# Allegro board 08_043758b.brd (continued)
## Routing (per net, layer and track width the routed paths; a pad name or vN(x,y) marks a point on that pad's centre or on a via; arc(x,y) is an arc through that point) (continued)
1P3_SUPPLY_B: length 107.7
  TOP w0.203: U1.9 20.63,14.51 20.47,14.68 20.1,14.68
  TOP w0.305: C5.1 19.1,16.14 ; C5.1 18.64,15.73 ; C5.1 18.18,16.14 ; U5.A7 v2(34.74,31.28) ; U5.E3 v2(31.54,35.28) ; 16.98,12.21 U1.14 U1.13 ; U5.A8 v2(33.94,31.28) ; U5.K4 v2(26.74,34.48) ; U1.11 U1.12 ; U1.11 19.33,14.56 ; U1.11 U1.10 19.98,14.56 ; U1.12 18.68,14.56 ; U1.12 18.25,13.78 ; U5.A9 v2(34.74,30.48) ; 16.98,12.86 U1.13 ; U1.13 17.76,13.29 ; U5.A10 v2(34.74,29.68) ; 19.91,15.73 C6.1 ; C6.1 20.37,16.14 ; C6.1 19.45,16.14 ; U5.D2 v2(32.34,36.08) ; U5.F12 v2(30.74,27.28) ; 20.93,16.08 UNK1P3V_B.1 21.69,15.31 ; U5.M10 v2(25.14,28.88) ; U5.M9 v2(25.14,29.68) ; U5.B8 v2(33.94,30.48) ; U5.D3 v2(32.34,35.28)
  TOP w0.635: L8.1 22.17,27.63 v1(21.14,27.63) ; C3.1 16.93,14.3 ; C3.1 16.29,15 ; C3.1 16.29,13.6 ; L9.1 v1(21.14,33.09) ; 16.42,16.01 C4.1 ; C4.1 17.12,15.38 ; C4.1 17.82,16.01
  BOTTOM w0.305: C30.1 30.73,25.95 C26.1 30.73,27.26 v2(30.74,27.28) ; v2(26.74,34.48) 26.45,34.18 26.01,34.18 C41.1 25.68,33.84 C36.1 ; v2(33.94,30.48) 33.86,30.56 C27.1 33.86,31.2 v2(33.94,31.28) ; v1(21.14,27.63) 21.18,27.59 C129.2 20.74,27.06 19.98,26.3 C130.1
  BOTTOM w0.406: v2(34.74,30.48) 34.74,30.48 v2(33.94,30.48) ; v2(34.74,30.48) 34.74,31.28 v2(34.74,31.28) ; v2(34.74,30.48) 35.15,30.48 35.41,30.74 35.41,31.2 35.49,31.28 ; v2(34.74,30.48) 34.74,29.68 v2(34.74,29.68) ; C31.1 35.49,31.28 ; 35.49,31.28 34.75,31.28 v2(34.74,31.28) ; v2(34.74,31.28) v2(33.94,31.28) ; v2(31.54,35.28) v2(32.34,35.28) 32.34,35.37 ; 32.34,35.37 v2(32.34,36.08) ; 32.34,35.37 32.47,35.49 C42.1 33.83,35.49 C37.1
  BOTTOM w0.508: C36.1 23.96,34.36 16.73,34.36 v1(14.91,36.18) v1(14.09,36.18) ; v1(21.14,33.09) v1(21.14,27.63) 23.9,27.63 v2(25.14,28.88) 25.14,29.68 v2(25.14,29.68) ; v1(33.24,43.19) v1(33.24,42.39) 33.24,39.38 35.5,37.13 35.5,35.73 35.14,35.37 C37.1 ; C31.1 36.3,31.33 36.75,31.78 36.75,37.68 34.55,39.88 v1(34.55,42.39) v1(34.55,43.19)
  BOTTOM w0.635: C130.1 15.11,26.3 v1(14.91,26.5) v1(14.09,26.5) ; E3.2 v1(33.63,56.97) ; C30.1 30.9,23.63 29.94,22.68 23.85,22.68 v1(21.82,20.65) v1(21.05,20.65)
  vias: v1(16.23,16.08) v1(16.23,15.19) v1(17.12,15.19) v1(17.24,14.3) v1(18.01,16.08) v1(18.01,15.19) v1(19.28,16.08) v1(20.55,16.08)
1P8V_CLK: length 11.9
  TOP w0.305: Y3.4 25.06,17.67 C122.1 25.06,14.58 C121.1 25.37,14.21 v1(25.37,13.28) ; 47.61,15.71 U12.1 48.29,16.12 ; 45.82,16.33 UNK1P8V_CLK.1 45.06,15.57
  TOP w0.508: 46,15.55 C170.1 ; C170.1 46.58,16.1 ; C170.1 47.17,15.55
  L6_SIG w0.305: UNK1P8V_CLK.1 45.82,16.33 ; UNK1P8V_CLK.1 45.06,15.57 ; UNK1P8V_CLK.1 45.06,17.09 ; UNK1P8V_CLK.1 44.3,16.33
  vias: v1(46.2,16.33) v1(46.96,16.33)
AD9363_AUXADC: length 49.2
  TOP w0.127: U5.L5 v2(25.95,32.88)
  L6_SIG w0.127: ADC.1 42.64,67 36.04,67 35.53,66.49 35.53,63.32 29.85,57.63 29.85,50.29 30.55,49.59 30.55,39.78 27.95,37.18 27.95,34.28 27.77,34.1 27.27,34.1 27.14,33.98 27.14,33.48 26.94,33.28 U5.L5 v2(25.95,32.88)
AD9363_AUXDAC1: length 39.8
  TOP w0.127: U5.B3 33.95,35.08 34.15,35.28 35.25,35.28 35.55,35.58 35.55,38.79 36.62,39.86 v1(36.62,41.16)
  L6_SIG w0.127: DAC1.1 37.92,64.11 37.92,61.77 37.31,61.16 34.39,61.16 30.91,57.68 30.91,50.86 33.91,47.86 33.91,45.96 36.62,43.26 v1(36.62,41.16)
AD9363_AUXDAC2: length 35.1
  TOP w0.127: v1(35.92,42.16) 35.92,39.66 35.25,38.99 35.25,38.18 33.95,36.88 33.95,35.48 33.74,35.28 33.15,35.28 U5.C3
  L6_SIG w0.127: v1(35.92,42.16) 35.92,43.46 33.51,45.86 33.51,47.66 30.51,50.66 30.51,57.79 35.41,62.68 DAC2.1
AD9363_GPO_0: length 45.7
  TOP w0.127: U5.B7 33.94,32.08 35.65,32.08 36.75,33.18 36.75,37.88 39.02,40.16 v1(39.02,41.16)
  L6_SIG w0.127: v1(39.02,41.16) 39.02,42.86 35.52,46.36 35.52,48.66 32.51,51.66 32.51,57.25 34.87,59.61 41.35,59.61 GPO0.1
AD9363_GPO_1: length 43
  TOP w0.127: U5.B6 33.94,32.88 35.45,32.88 36.45,33.88 36.45,38.18 38.42,40.16 v1(38.42,42.16)
  L6_SIG w0.127: GPO1.1 41.88,61.54 40.35,60.01 34.76,60.01 32.11,57.36 32.11,51.46 35.12,48.46 35.12,46.26 38.42,42.96 v1(38.42,42.16)
AD9363_GPO_2: length 39.8
  TOP w0.127: U5.B5 33.94,33.68 35.35,33.68 36.15,34.48 36.15,38.38 37.82,40.06 v1(37.82,41.16)
  L6_SIG w0.127: v1(37.82,41.16) 37.82,43.06 34.72,46.16 34.72,48.26 31.71,51.26 31.71,57.47 34.66,60.41 38.21,60.41 39.34,61.54 GPO2.1
AD9363_GPO_3: length 40.9
  TOP w0.127: U5.B4 33.94,34.48 35.15,34.48 35.85,35.18 35.85,38.59 37.22,39.96 v1(37.22,42.16)
  L6_SIG w0.127: v1(37.22,42.16) 37.22,43.16 34.31,46.06 34.31,48.06 31.31,51.06 31.31,57.58 34.55,60.81 37.47,60.81 38.22,61.56 38.22,64.1 GPO3.1
ADM1177_SCL: length 61
  TOP w0.127: v1(73.89,15.06) 73.04,14.21 66.79,14.21 66.69,14.11 65.26,14.11 R81.2 64.18,15.19 U11.7
  L5_SIG w0.127: v1(86.36,56.63) 85.71,56.63 84.78,55.7 84.78,38.93 78.11,32.26 78.11,27.65 78.62,27.14 78.62,21.47 76.95,19.8 76.95,18.78 73.89,15.72 v1(73.89,15.06)
  BOTTOM w0.127: v1(86.36,56.63) 86.36,57.32 86.13,57.55 U10.6
ADM1177_SDA: length 64.7
  TOP w0.127: v1(74.78,15.69) 74.78,15.06 73.54,13.83 65.24,13.83 R80.2 63.98,13.87 63.98,14.3 63.74,14.54 U11.6
  L5_SIG w0.127: v1(87.6,56.63) 86.97,55.99 85.58,55.99 85.14,55.55 85.14,38.78 78.47,32.12 78.47,27.8 78.98,27.29 78.98,21.32 77.33,19.67 77.33,18.53 75.55,16.75 75.55,16.47 v1(74.78,15.69)
  BOTTOM w0.127: U10.7 87.03,58.05 87.6,57.48 v1(87.6,56.63)
ADP2114_VIN: length 20
  TOP w0.203: 93.57,40.97 93.3,41.24 U6.31
  TOP w0.305: C141.1 95.24,47.57 93.6,47.57 93.3,47.27 U6.10 ; C141.1 96.18,46.99 R56.2 96.18,48.27 v1(95.98,48.46) ; C141.1 95.21,46.02 U6.8 ; 93.57,40.97 93.95,40.59 v1(94.71,40.59) ; v1(95.35,44.14) 95.23,44.02 U6.4
  L5_SIG w0.305: v1(94.71,40.59) 95.22,40.59 96.1,41.46 96.1,43.02 95.35,43.76 v1(95.35,44.14) 95.68,44.14 95.98,44.45 v1(95.98,48.46)
COMP_1P8V: length 2.8
  TOP w0.305: U6.2 95.2,43.02 v1(95.35,42.87)
  BOTTOM w0.508: v1(95.35,42.87) 95.48,42.75 R60.1 C142.2
COMP_1P35V: length 3.1
  TOP w0.305: C144.1 C143.2 96.1,45.52 U6.7
CTRL_IN0: length 52
  TOP w0.102: U4.F13 v2(56.33,28.95) ; U5.C5 v2(33.14,33.68)
  L6_SIG w0.114: v2(33.14,33.68) 33.15,33.68 33.55,34.08 33.55,34.68 33.35,34.88 31.35,34.88 30.34,33.88 30.34,32.68 30.15,32.48 28.65,32.48 27.95,31.78 27.95,24.43 30.2,22.17 53.36,22.17 56.72,25.53 56.72,26.91 56.33,27.31 v2(56.33,28.95)
CTRL_IN1: length 47.2
  TOP w0.102: U5.C6 v2(33.14,32.88) ; U4.F14 55.93,28.54 56.33,28.14 v2(56.33,26.55)
  L6_SIG w0.114: v2(56.33,26.55) 56.33,25.74 53.27,22.68 30.33,22.68 28.35,24.66 28.35,30.68 28.74,31.07 28.74,31.58 28.84,31.68 29.35,31.68 29.71,32.05 30.11,32.05 30.82,32.75 30.82,33.15 31.75,34.08 32.55,34.08 32.75,33.88 32.75,33.28 33.14,32.89 v2(33.14,32.88)
CTRL_IN2: length 37.7
  TOP w0.102: U5.D6 v2(32.34,32.88) ; v2(55.53,27.35) U4.G15
  L6_SIG w0.114: v2(55.53,27.35) 54.96,26.78 54.96,26.37 54.66,26.07 54.06,26.07 52.19,24.2 31.82,24.2 31.25,24.77 31.25,25.57 30.05,26.77 30.05,28.07 29.55,28.57 29.55,30.68 29.75,30.88 30.15,30.88 30.35,31.08 30.35,31.48 31.22,32.35 31.61,32.35 32.14,32.88 v2(32.34,32.88)
CTRL_IN3: length 41.3
  TOP w0.102: v2(55.53,26.55) 55.93,26.95 U4.F15 ; U5.D5 v2(32.34,33.68)
  L6_SIG w0.114: v2(32.34,33.68) U5.D5 31.34,33.28 31.12,33.05 31.12,32.65 30.17,31.7 29.76,31.7 29.55,31.48 29.55,31.08 29.35,30.88 28.95,30.88 28.75,30.68 28.75,28.17 29.25,27.67 29.25,25.28 30.71,23.82 52.61,23.82 53.98,25.18 54.97,25.18 55.53,25.75 v2(55.53,26.55)
DDR3_A0: length 30.1
  TOP w0.165: U2.N3 51.22,54.27 v2(51.22,54.27) ; v2(43.92,40.85) 47.03,40.85 48.43,39.45 49.03,39.45 U4.P1
  L6_SIG w0.165: v2(43.92,40.85) 43.32,41.45 43.32,42.04 43.52,42.23 43.91,42.23 44.11,42.43 44.11,42.71 43.91,42.91 43.52,42.91 43.32,43.1 43.32,43.38 43.52,43.58 43.91,43.58 44.11,43.78 44.11,44.06 43.91,44.25 43.52,44.25 43.32,44.45 43.32,47.48 46.51,50.67 49.02,50.67 49.41,51.07 49.41,51.87 51.22,53.68 v2(51.22,54.27)
  BOTTOM w0.165: R16.1 51.62,56.16 51.62,54.67 v2(51.22,54.27)
DDR3_A1: length 33.2
  TOP w0.165: v2(43.92,41.65) 46.93,41.65 48.63,39.95 49.33,39.95 U4.N1 ; v2(48.03,51.66) 49.83,51.66 U2.P7
  L6_SIG w0.165: v2(43.92,41.65) 44.41,41.16 44.41,39.66 44.21,39.46 43.61,39.46 42.51,40.56 42.51,48.17 42.72,48.38 42.72,48.78 43.07,49.13 43.47,49.13 43.67,49.33 43.67,49.61 43.4,49.88 43.4,50.16 43.6,50.35 43.88,50.35 44.15,50.08 44.43,50.08 44.62,50.28 44.62,50.56 44.35,50.83 44.35,51.11 44.55,51.31 44.83,51.31 45.1,51.03 45.38,51.03 46,51.66 v2(48.03,51.66)
  BOTTOM w0.165: R22.1 47.45,51.66 v2(48.03,51.66)
DDR3_A2: length 35.7
  TOP w0.165: U2.P3 v2(50.42,54.27) ; U4.M1 51.13,39.75 v2(49.93,40.95)
  L5_SIG w0.165: v2(49.93,40.95) 49.53,40.95 49.23,40.65 49.23,40.35 49.93,39.65 49.93,39.35 49.53,38.95 49.53,37.95 49.13,37.55 48.93,37.55 48.73,37.75 48.73,38.75 48.53,38.95 48.23,38.95 48.03,38.75 48.03,37.65 47.87,37.49 47.59,37.49 45.83,39.25 45.83,51.2 48.5,53.87 50.02,53.87 v2(50.42,54.27)
  BOTTOM w0.165: v2(50.42,54.27) 50.02,53.87 49.3,53.87 48.61,54.56 47.45,54.56 R17.1
DDR3_A3: length 31.5
  TOP w0.165: U4.M4 v2(50.73,36.95) ; U2.N2 v2(51.22,55.07)
  L5_SIG w0.165: v2(50.73,36.95) 51.02,36.95 51.13,37.06 51.13,37.97 51.48,38.33 51.48,38.63 51.28,38.83 50.9,38.83 50.73,39 50.73,42.75 50.53,42.95 49.93,42.95 49.53,43.35 49.53,44.55 49.71,44.73 50.13,44.73 50.33,44.93 50.33,45.21 50.13,45.4 49.73,45.4 49.53,45.6 49.53,45.88 49.73,46.08 50.13,46.08 50.33,46.27 50.33,46.55 50.13,46.75 49.73,46.75 49.53,46.95 49.53,47.23 49.73,47.42 50.13,47.42 50.33,47.62 50.33,48.06 50.12,48.27 49.92,48.27 49.73,48.46 49.73,49.56 50.04,49.87 50.64,49.87 50.82,50.04 50.82,51.73 51,51.92 51.51,51.92 51.69,52.09 51.69,52.58 51.85,52.74 52.59,52.74 52.75,52.9 52.75,53.12 52.59,53.28 51.85,53.28 51.69,53.44 51.69,53.74 51.85,53.9 52.6,53.9 52.76,54.06 52.76,54.28 52.6,54.44 51.65,54.44 51.46,54.63 51.46,54.83 v2(51.22,55.07)
  BOTTOM w0.165: v2(51.22,55.07) 50.94,55.07 50.82,55.2 50.82,56.16 R23.1
DDR3_A4: length 26.7
  TOP w0.165: v2(47.33,38.65) 48.23,37.75 49.13,37.75 U4.P3 ; v2(50.42,50.27) U2.P8
  L6_SIG w0.165: v2(50.42,50.27) 50.83,49.86 50.83,48.28 50.62,48.07 49.82,48.07 46.41,44.66 46.41,41.76 46.71,41.46 48.91,41.46 49.13,41.25 49.13,40.75 48.84,40.46 48.04,40.46 47.81,40.23 47.81,39.66 47.61,39.46 46.71,39.46 46.51,39.26 46.51,38.46 46.72,38.25 46.93,38.25 v2(47.33,38.65)
  BOTTOM w0.165: R18.1 47.64,50.67 50.02,50.67 v2(50.42,50.27)
DDR3_A5: length 24
  TOP w0.165: U2.P2 v2(50.42,55.07) ; v2(49.11,36.96) U4.P4
  L5_SIG w0.165: v2(49.11,36.96) 49.5,37.35 50.13,37.35 50.33,37.55 50.33,38.05 50.33,38.05 50.45,38.17 50.45,38.73 50.33,38.85 50.33,42.35 50.13,42.55 49.73,42.55 49.13,43.15 49.13,48.16 49.33,48.36 49.33,49.78 50.43,50.88 50.43,51.98 51.23,52.78 51.23,53.56 50.82,53.97 50.82,54.67 v2(50.42,55.07)
  BOTTOM w0.165: v2(50.42,55.07) 50.14,55.07 50.02,55.2 50.02,56.16 R24.1
DDR3_A6: length 26.8
  TOP w0.165: U2.R8 49.62,49.47 48.81,49.47 v2(48.01,48.67) ; v2(46.72,36.55) 47.13,36.15 49.13,36.15 U4.P5
  L6_SIG w0.165: v2(46.72,36.55) 44.91,38.36 44.91,38.86 45.21,39.16 45.21,44.26 44.21,45.26 44.21,47.07 44.82,47.67 45.1,47.67 45.37,47.4 45.65,47.4 45.84,47.6 45.84,47.88 45.61,48.11 45.61,48.47 46.01,48.87 46.29,48.87 46.42,48.74 46.42,47.96 46.63,47.76 47.13,47.76 47.33,47.96 47.33,48.26 47.09,48.49 47.09,48.87 47.29,49.07 47.62,49.07 v2(48.01,48.67)
  BOTTOM w0.165: v2(48.01,48.67) 48.52,48.17 48.63,48.17 R19.1
DDR3_A7: length 30.3
  TOP w0.165: U4.M5 v2(50.73,36.15) ; U2.R2 v2(49.62,55.07)
  L5_SIG w0.165: v2(50.73,36.15) 50.33,35.75 49.03,35.75 48.63,36.15 47.73,36.15 46.57,37.3 45.67,37.3 45.02,37.95 45.02,51.58 48.82,55.37 49.31,55.37 v2(49.62,55.07)
  BOTTOM w0.165: v2(49.62,55.07) 49.33,55.36 48.63,55.36 48.12,55.87 R25.1
DDR3_A8: length 24.1
  TOP w0.165: U4.P6 49.13,35.35 47.12,35.35 v2(46.72,35.75) ; v2(48.01,49.47) 48.41,49.87 U2.T8
  L6_SIG w0.165: v2(46.72,35.75) 46.42,36.16 44.51,38.06 44.51,39.16 44.81,39.46 44.81,44.06 43.81,45.06 43.81,47.27 46.01,49.47 v2(48.01,49.47)
  BOTTOM w0.165: v2(48.01,49.47) 47.52,48.97 47.52,48.55 R20.1
DDR3_A9: length 27.7
  TOP w0.165: U4.N4 v2(49.93,36.95) ; v2(49.61,54.27) U2.R3
  L5_SIG w0.165: v2(49.61,54.27) 48.34,54.27 45.43,51.36 45.43,39.05 47.43,37.05 48.33,37.05 48.93,36.45 49.43,36.45 v2(49.93,36.95)
  BOTTOM w0.165: R26.1 47.87,54.94 48.95,54.94 v2(49.61,54.27)
DDR3_A10: length 39.2
  TOP w0.165: U4.J1 53.13,39.35 v2(53.13,40.35) ; v2(52.81,51.07) 53.21,50.67 U2.L7
  L5_SIG w0.165: v2(52.81,51.07) 53.23,50.66 53.48,50.66 53.63,50.51 53.63,50.1 53.13,49.6 53.13,48.8 52.93,48.6 52.63,48.6 52.43,48.41 52.43,48.13 52.63,47.93 53.43,47.93 53.63,47.73 53.63,47.35 53.43,47.15 52.43,47.15 52.43,47.16 52.13,47.46 51.83,47.46 51.63,47.26 51.63,46.62 51.83,46.41 52.23,46.41 52.43,46.22 52.43,45.94 52.23,45.74 51.83,45.74 51.63,45.54 51.63,45.15 51.92,44.87 52.24,44.87 52.73,45.36 53.03,45.36 53.23,45.16 53.23,44.41 53.1,44.28 52.35,44.28 52.13,44.06 52.13,43.86 52.32,43.67 53.1,43.67 53.32,43.45 53.32,43.22 53.03,42.93 52.73,42.93 52.53,42.74 52.53,42.46 52.73,42.26 52.93,42.26 53.13,42.06 53.13,41.79 52.93,41.59 52.73,41.59 52.32,41.18 52.32,40.36 52.73,39.95 52.73,35.95 52.93,35.75 54.13,35.75 54.33,35.95 54.33,36.25 54.13,36.45 53.68,36.45 53.53,36.6 53.53,39.95 v2(53.13,40.35)
  BOTTOM w0.165: v2(52.81,51.07) 52.22,51.07 51.62,50.47 51.62,48.28 R21.1
DDR3_A11: length 32.7
  TOP w0.165: v2(47.43,42.05) 48,41.48 50,41.48 51.53,39.95 51.53,38.55 U4.L2 ; U2.R7 49.62,50.27 v2(48.02,50.27)
  L5_SIG w0.165: v2(47.43,42.05) 47.43,41.34 46.81,40.72 46.81,39.87 47.13,39.55 47.63,39.55 47.98,39.9 47.98,41.1 48.33,41.45 48.73,41.45 48.93,41.65 48.93,42.75 48.43,43.25 47.73,43.25 47.53,43.45 47.53,43.76 47.72,43.95 48.53,43.95 48.73,44.15 48.73,44.43 48.53,44.63 47.82,44.63 47.63,44.82 47.63,45.1 47.82,45.3 48.53,45.3 48.73,45.5 48.73,45.77 48.53,45.97 47.82,45.97 47.63,46.17 47.63,46.45 47.82,46.65 48.53,46.65 48.73,46.84 48.73,47.12 48.53,47.32 47.82,47.32 47.63,47.52 47.63,47.96 47.83,48.16 48.23,48.16 48.42,48.35 48.42,48.87 48.22,49.07 47.81,49.07 47.62,49.27 47.62,49.87 v2(48.02,50.27)
  BOTTOM w0.165: R27.1 47.23,49.49 v2(48.02,50.27)
DDR3_A12: length 30.5
  TOP w0.165: U4.M2 50.75,38.52 50.75,39.34 49.14,40.95 v2(48.43,40.95) ; U2.N7 51.22,51.07 v2(51.22,51.07)
  L6_SIG w0.165: v2(48.43,40.95) 46.32,40.95 46.01,41.26 46.01,45.46 45.81,45.66 45.31,45.66 45.09,45.88 45.09,46.35 45.31,46.57 47.71,46.57 50.03,48.88 50.03,49.19 49.83,49.38 49.51,49.38 49.31,49.58 49.31,49.86 49.51,50.06 49.83,50.06 50.01,50.24 50.01,50.54 50.53,51.06 50.53,51.79 51.5,52.76 51.73,52.76 51.98,52.51 51.98,52.21 51.22,51.44 v2(51.22,51.07)
  BOTTOM w0.165: v2(51.22,51.07) 50.82,50.67 50.82,48.28 R28.1
DDR3_A13: length 30.8
  TOP w0.165: v2(49.93,41.98) 50.23,41.98 52.33,39.89 52.33,38.55 U4.K2 ; v2(48.82,53.47) 48.82,53.47 U2.T3
  L5_SIG w0.165: v2(48.82,53.47) 48.2,52.86 48.03,52.86 46.23,51.06 46.23,50.52 46.35,50.39 46.63,50.39 46.83,50.2 46.83,49.92 46.63,49.72 46.42,49.72 46.23,49.52 46.23,49.24 46.42,49.05 46.63,49.05 46.83,48.85 46.83,48.57 46.63,48.37 46.42,48.37 46.23,48.18 46.23,47.9 46.42,47.7 46.63,47.7 46.83,47.5 46.83,47.23 46.63,47.03 46.42,47.03 46.23,46.83 46.23,46.55 46.63,46.15 46.63,45.75 46.23,45.35 46.23,39.65 46.72,39.15 47.83,39.15 48.83,40.15 48.83,40.88 v2(49.93,41.98)
  BOTTOM w0.165: v2(48.82,53.47) 48.22,54.07 R34.1
DDR3_A14: length 35.5
  TOP w0.165: U4.K1 52.73,40.09 50.32,42.49 48.87,42.49 v2(48.43,42.05) ; v2(48.82,51.07) U2.T7
  L5_SIG w0.165: v2(48.82,51.07) 49.23,50.66 49.23,50.26 48.92,49.95 48.74,49.95 48.53,50.16 48.53,50.46 48.13,50.86 48.13,51.16 48.83,51.86 49.08,51.86 49.59,51.36 49.83,51.36 50.03,51.56 50.03,51.87 49.57,52.32 49.57,52.6 49.73,52.76 50.03,52.76 50.23,52.56 50.5,52.56 50.71,52.78 50.71,53.24 50.5,53.45 49.62,53.45 48.24,52.07 47.84,52.07 47.61,51.84 47.61,51.5 47.38,51.27 47.04,51.27 46.83,51.06 46.83,50.86 47.22,50.47 47.22,45.38 47.03,45.19 46.82,45.19 46.63,45 46.63,44.72 46.82,44.52 47.03,44.52 47.23,44.32 47.23,44.04 47.03,43.85 46.82,43.85 46.63,43.65 46.63,42.55 46.79,42.39 47.07,42.39 47.43,42.75 48.3,42.75 48.43,42.63 v2(48.43,42.05)
  BOTTOM w0.165: R29.1 48.02,51.07 48.46,51.51 48.69,51.51 48.82,51.39 v2(48.82,51.07)
DDR3_BA0: length 34
  TOP w0.165: U2.M2 v2(52.02,55.07) ; U4.M6 v2(50.73,35.35)
  L5_SIG w0.165: v2(50.73,35.35) 51.13,35.75 51.73,35.75 51.93,35.94 51.93,38.75 51.13,39.55 51.13,43.24 50.93,43.44 50.13,43.44 49.93,43.64 49.93,43.92 50.13,44.11 50.6,44.11 50.82,44.33 50.82,48.17 50.93,48.28 50.93,49.36 51.62,50.04 51.62,50.52 51.84,50.74 51.84,51.69 52.14,51.99 53.57,51.99 53.87,52.3 53.87,52.75 53.64,52.98 53.39,52.98 53.22,53.15 53.22,57.57 53.02,57.78 52.77,57.78 52.58,57.58 52.58,55.63 v2(52.02,55.07)
  BOTTOM w0.165: R35.1 52.72,55.57 52.52,55.37 52.32,55.37 v2(52.02,55.07)
DDR3_BA1: length 30.4
  TOP w0.165: v2(51.22,50.27) U2.N8 ; U4.R1 48.35,38.95 v2(47.34,39.96)
  L6_SIG w0.165: v2(51.22,50.27) 51.22,48.07 50.8,47.65 50,47.65 48.13,45.78 48.13,44.95 47.76,44.59 47.34,44.59 47.11,44.36 47.11,44.14 47.34,43.91 47.76,43.91 48,43.68 48,43.36 47.83,43.2 47.44,43.2 47.21,42.97 47.21,42.75 47.44,42.52 49.33,42.52 49.53,42.33 49.53,40.27 49.11,39.86 48.51,39.86 48.23,39.57 48.23,38.85 47.33,37.95 47.33,37.47 47.05,37.2 46.67,37.2 46.11,37.76 46.11,40.36 46.28,40.53 47.14,40.53 47.34,40.34 v2(47.34,39.96)
  BOTTOM w0.165: R30.1 51.22,47.89 v2(51.22,50.27)
DDR3_BA2: length 28.7
  TOP w0.165: U2.M3 52.42,53.37 v2(53.32,52.47) ; U4.N6 v2(49.93,35.35)
  L6_SIG w0.165: v2(49.93,35.35) 50.33,35.75 50.98,35.75 51.13,35.9 51.13,36.38 50.97,36.55 50.57,36.55 50.33,36.78 50.33,38.97 51.02,39.66 51.41,39.66 51.72,39.96 51.72,40.86 51.32,41.26 51.32,43.66 50.63,44.35 50.33,44.35 49.93,43.95 49.63,43.95 49.43,44.15 49.43,45.18 50.7,46.45 52.13,46.45 52.33,46.65 52.33,47.15 53.21,48.04 53.21,51.36 54.02,52.17 54.02,52.57 53.82,52.76 53.61,52.76 v2(53.32,52.47)
  BOTTOM w0.165: R36.1 52.54,51.69 v2(53.32,52.47)
DDR3_CAS#: length 28.5
  TOP w0.165: v2(53.62,53.46) 54.02,53.86 U2.K3 ; v2(48.21,35.75) U4.R5
  L6_SIG w0.165: v2(48.21,35.75) 48.78,35.18 49.16,35.18 49.43,35.45 49.43,36.02 49.3,36.15 48.93,36.15 48.65,36.43 48.65,37.47 48.81,37.64 49.36,37.64 49.53,37.8 49.53,38.87 50.83,40.17 50.83,43.15 50.52,43.46 49.22,43.46 49.01,43.67 49.01,45.36 50.52,46.87 51.32,46.87 52.73,48.28 52.73,50.36 52.22,50.87 52.22,51.14 52.82,51.74 52.82,52.66 v2(53.62,53.46)
  BOTTOM w0.165: v2(53.62,53.46) 53.63,53.45 53.63,53.01 53.49,52.87 52.94,52.87 R32.1
DDR3_CK_N: length 32.4
  TOP w0.127: v2(53.61,51.07) 54.02,50.67 U2.K7 ; U4.N2 v2(49.93,38.55)
  BOTTOM w0.127: R142.2 53.61,51.66 v2(53.61,51.07) 53.22,50.68 53.22,50.44 53.43,50.23 53.61,50.23 53.94,50.56 54.12,50.56 54.42,50.26 54.42,47.57 55.09,46.9 58.79,46.9 59.14,46.55 59.14,46.06 58.82,45.74 54.85,45.74 54.32,45.21 54.32,44.15 54.06,43.89 51.99,43.89 50.81,45.06 49.92,45.06 49.12,44.26 49.12,43.5 50.95,41.66 50.95,38.95 50.3,38.3 50.18,38.3 v2(49.93,38.55)
DDR3_CK_P: length 31.5
  TOP w0.127: U4.N3 v2(49.93,37.75) ; U2.J7 v2(54.42,51.07)
  BOTTOM w0.127: v2(49.93,37.75) 50.2,38.02 50.41,38.02 51.23,38.84 51.23,41.78 49.4,43.62 49.4,44.15 50.03,44.78 50.7,44.78 51.87,43.61 54.18,43.61 54.6,44.03 54.6,45.09 54.97,45.46 58.94,45.46 59.42,45.94 59.42,46.66 58.91,47.18 55.21,47.18 54.7,47.69 54.7,50.38 54.42,50.66 v2(54.42,51.07) 54.42,51.47 R142.1
DDR3_CKE: length 34.9
  TOP w0.165: U4.L3 v2(51.53,37.75) ; v2(53.62,48.67) U2.K9
  L6_SIG w0.165: v2(51.53,37.75) U4.L3 53.4,37.35 53.63,37.58 53.63,37.93 53.41,38.15 52.83,38.15 52.64,38.35 51.03,38.35 50.86,38.52 50.86,38.79 51.02,38.96 53.4,38.96 53.64,39.2 53.64,39.58 53.38,39.85 52.33,39.85 52.13,40.04 52.13,40.32 52.33,40.52 52.53,40.52 52.73,40.72 52.73,41.01 52.53,41.21 52.13,41.21 51.93,41.4 51.93,41.68 52.13,41.88 53,41.88 53.13,42.01 53.13,42.42 53,42.55 52.33,42.55 52.13,42.75 52.13,43.05 52.3,43.22 53.28,43.22 53.43,43.38 53.43,43.75 53.28,43.9 51.73,43.9 51.53,44.09 51.53,44.37 51.73,44.57 52.93,44.57 53.13,44.77 53.13,45.05 52.93,45.24 51.32,45.24 51.03,44.95 50.73,44.95 50.53,45.15 50.53,45.45 50.99,45.92 53.29,45.92 53.62,46.24 v2(53.62,48.67)
  BOTTOM w0.165: R38.1 53.63,47.88 53.82,48.07 53.82,48.47 v2(53.62,48.67)
DDR3_CS#: length 29.4
  TOP w0.165: U4.R2 48.47,38.15 47.37,39.25 46.32,39.25 45.63,39.95 v2(43.92,39.95) ; U2.L2 v2(52.82,55.07)
  L6_SIG w0.165: v2(43.92,39.95) 42.92,40.95 42.92,47.68 46.31,51.07 48.11,51.07 50.82,53.78 50.82,54.48 51.01,54.67 52.23,54.67 v2(52.82,55.07)
  BOTTOM w0.165: v2(52.82,55.07) 53.09,55.07 53.22,55.2 53.22,56.15 R39.1
DDR3_DM0: length 26.5
  TOP w0.165: U4.B1 60.01,39.82 62.25,39.82 v2(63.13,38.95) ; U2.E7 59.22,51.87 v2(59.22,52.67)
  L6_SIG w0.165: v2(59.22,52.67) 59.62,52.27 62.63,52.27 63.52,51.37 63.52,50.49 63.2,50.16 63.2,49.89 63.4,49.69 63.68,49.69 63.9,49.91 64.18,49.91 64.53,49.56 64.53,40.35 v2(63.13,38.95)
DDR3_DM1: length 23.1
  TOP w0.165: v2(59.22,53.47) U2.D3 ; U4.D3 v2(57.93,37.75)
  L5_SIG w0.165: v2(59.22,53.47) 58.52,52.78 58.52,51.05 58.02,50.54 58.02,48.16 55.63,45.78 55.63,42.35 54.23,40.95 54.23,37.55 54.42,37.35 57.53,37.35 v2(57.93,37.75)
DDR3_DQ0: length 28.4
  TOP w0.165: U2.E3 58.42,54.27 v2(58.42,54.27) ; U4.D4 v2(57.93,36.95)
  L6_SIG w0.165: v2(58.42,54.27) 58.81,54.27 58.99,54.09 58.99,53.88 58.77,53.67 58.77,52.42 59.72,51.47 61.92,51.47 62.63,50.76 62.63,49.26 63.03,48.85 63.31,48.85 63.48,49.02 63.76,49.02 63.96,48.83 63.96,48.55 63.79,48.38 63.79,48.1 64.13,47.76 64.13,40.65 62.63,39.15 62.63,37.95 61.23,36.55 58.33,36.55 v2(57.93,36.95)
DDR3_DQ1: length 24.7
  TOP w0.165: v2(58.02,52.27) 57.22,51.47 U2.F7 ; U4.A2 61.73,38.15 v2(62.13,38.55)
  L6_SIG w0.165: v2(58.02,52.27) 59.62,50.67 61.92,50.67 62.12,50.47 62.12,48.6 62.29,48.43 62.77,48.43 62.93,48.26 62.93,47.93 62.77,47.77 62.24,47.77 62.07,47.6 62.07,47.27 62.24,47.11 63.47,47.11 63.63,46.94 63.63,40.97 63.32,40.66 62.72,40.66 62.13,40.07 v2(62.13,38.55)
DDR3_DQ2: length 23.2
  TOP w0.165: U4.C4 v2(58.73,36.95) ; U2.F2 v2(56.82,55.07)
  L6_SIG w0.165: v2(58.73,36.95) 58.33,37.35 56.94,37.35 56.73,37.56 56.73,39.05 55.13,40.65 55.13,41.15 54.73,41.55 54.73,43.15 54.41,43.47 54.41,49.87 54.82,50.27 54.82,53.68 55.81,54.67 56.42,54.67 v2(56.82,55.07)
DDR3_DQ3: length 28.4
  TOP w0.165: v2(61.63,40.65) 60.03,40.65 U4.C1 ; v2(58.02,51.47) 57.62,51.07 57.62,50.27 U2.F8
  L6_SIG w0.165: v2(58.02,51.47) 58.02,51.37 59.33,50.06 60.33,50.06 60.53,49.86 60.53,49 60.69,48.84 60.98,48.84 61.15,48.67 61.15,48.34 60.98,48.18 60.69,48.18 60.53,48.01 60.53,47.45 61.35,46.63 62.93,46.63 63.13,46.43 63.13,46.13 62.89,45.89 61.65,45.89 61.42,45.66 61.42,45.36 61.62,45.16 62.97,45.16 63.14,44.99 63.14,44.66 62.97,44.5 62.2,44.5 62.03,44.33 62.03,44 62.2,43.84 62.97,43.84 63.14,43.67 63.14,43.34 62.97,43.18 62.4,43.18 62.23,43.01 62.23,42.68 62.4,42.52 62.97,42.52 63.14,42.35 63.14,42.02 62.97,41.86 62.4,41.86 62.23,41.69 62.23,41.25 v2(61.63,40.65)
DDR3_DQ4: length 21.8
  TOP w0.165: v2(59.53,36.95) U4.B4 ; U2.H3 55.62,53.87 v2(56.83,52.66)
  L6_SIG w0.165: v2(56.83,52.66) 57.43,52.66 57.62,52.47 57.62,51.17 58.02,50.77 58.02,47.57 59.52,46.06 59.52,45.67 59.82,45.37 60.22,45.37 60.53,45.05 60.53,40.15 61.34,39.34 61.34,37.76 60.93,37.35 59.93,37.35 v2(59.53,36.95)
DDR3_DQ5: length 22.8
  TOP w0.165: v2(60.33,36.95) U4.A4 ; v2(58.42,47.87) 57.02,47.87 56.02,48.87 56.02,49.47 U2.H8
  L6_SIG w0.165: v2(58.42,47.87) 58.82,48.27 58.82,48.52 58.96,48.67 59.32,48.67 59.47,48.52 59.47,47.91 59.02,47.47 59.02,47.27 59.99,46.3 60.22,46.3 60.45,46.54 60.69,46.54 60.92,46.3 60.92,46.07 60.69,45.83 60.69,45.6 61.03,45.26 61.03,44.92 61.19,44.76 61.52,44.76 61.69,44.59 61.69,44.26 61.52,44.1 61.19,44.1 61.03,43.93 61.03,41.98 61.19,41.82 61.52,41.82 61.69,41.65 61.69,41.32 61.52,41.16 61.19,41.16 61.03,40.99 61.03,40.35 61.73,39.65 61.73,37.65 61.03,36.95 v2(60.33,36.95)
DDR3_DQ6: length 23.9
  TOP w0.165: U2.G2 v2(56.02,54.27) ; U4.C3 v2(58.73,37.75)
  L6_SIG w0.165: v2(58.73,37.75) 58.33,38.15 57.63,38.15 57.53,38.26 57.53,39.51 57.52,39.52 57.52,39.86 57.12,40.26 56.22,40.26 55.63,40.85 55.63,43.43 55.31,43.76 54.94,43.76 54.81,43.89 54.81,44.29 55.01,44.49 55.62,44.49 55.81,44.69 55.81,44.97 55.62,45.16 55.01,45.16 54.81,45.36 54.81,45.64 55.01,45.84 55.22,45.84 55.41,46.03 55.41,46.31 55.22,46.51 55.01,46.51 54.81,46.71 54.81,46.99 55.01,47.18 55.22,47.18 55.41,47.38 55.41,47.77 55.22,47.97 55.02,47.97 54.81,48.17 54.81,49.67 55.23,50.09 55.23,53.49 v2(56.02,54.27)
DDR3_DQ7: length 21.8
  TOP w0.165: U4.A3 v2(60.34,37.75) ; U2.H7 55.62,50.67 v2(56.82,51.87)
  L6_SIG w0.165: v2(56.82,51.87) 57.22,51.47 57.22,50.88 57.52,50.57 57.52,49.37 57.22,49.07 57.22,48.21 57.09,48.09 56.94,48.09 56.72,47.87 56.72,47.57 56.88,47.41 57.47,47.41 57.73,47.15 57.73,46.06 57.93,45.85 58.11,45.85 58.43,46.17 58.71,46.17 58.91,45.97 58.91,45.69 58.59,45.38 58.59,45.1 59.53,44.16 59.53,42.88 59.73,42.69 59.83,42.69 60.03,42.49 60.03,42.21 59.83,42.01 59.73,42.01 59.53,41.82 59.53,41.54 59.73,41.34 59.83,41.34 60.03,41.14 60.03,40.86 59.83,40.67 59.73,40.67 59.53,40.47 59.53,39.45 60.83,38.15 60.83,37.85 60.73,37.75 v2(60.34,37.75)
DDR3_DQ8: length 28.2
  TOP w0.165: U4.E1 56.73,38.95 57.13,39.35 v2(57.13,39.35) ; U2.D7 59.62,51.47 59.62,52.27 v2(60.02,52.67)
  L5_SIG w0.165: v2(57.13,39.35) 57.54,39.76 62.12,39.76 64.22,41.86 64.22,50.67 64.02,50.87 63.62,50.87 63.44,50.68 63.11,50.68 62.92,50.87 62.92,51.13 63.35,51.56 63.35,51.94 62.63,52.66 61.5,52.66 61.23,52.38 61.23,51.71 60.99,51.47 60.62,51.47 60.42,51.67 60.42,52.27 v2(60.02,52.67)
DDR3_DQ9: length 25.8
  TOP w0.165: v2(57.13,38.55) U4.D1 ; v2(60.02,53.47) U2.C3
  L5_SIG w0.165: v2(57.13,38.55) 57.63,39.05 59.83,39.05 60.03,38.85 60.63,38.85 61.14,39.36 62.32,39.36 64.92,41.96 64.92,49.59 64.62,49.89 64.62,50.25 64.72,50.35 64.72,51.17 62.52,53.37 62.22,53.37 61.91,53.06 60.43,53.06 v2(60.02,53.47)
DDR3_DQ10: length 28.6
  TOP w0.165: v2(61.62,50.26) 60.01,50.26 U2.C8 ; U4.E2 56.33,38.55 56.33,39.35 57.03,40.05 v2(57.03,41.05)
  L5_SIG w0.165: v2(61.62,50.26) 62.12,49.77 62.12,48.67 62.34,48.45 63.24,48.45 63.42,48.27 63.42,47.04 63.22,46.85 62.82,46.85 62.62,46.65 62.62,46.37 62.82,46.17 63.22,46.17 63.42,45.98 63.42,45.7 63.22,45.5 63.02,45.5 62.82,45.3 62.82,45.02 63.34,44.51 63.34,44.18 62.46,43.3 62.46,42.92 63.14,42.25 63.14,41.98 62.54,41.39 62.25,41.39 62.02,41.62 62.02,42.52 61.88,42.66 61.32,42.66 61.12,42.46 61.12,41.86 61.52,41.46 61.52,41.24 61.03,40.75 60.44,40.75 60.22,40.96 59.82,40.96 59.61,40.75 58.76,40.75 58.63,40.88 58.63,41.55 58.13,42.05 57.73,42.05 57.33,41.65 57.33,41.35 v2(57.03,41.05)
DDR3_DQ11: length 27
  TOP w0.165: v2(60.02,54.27) U2.C2 ; v2(57.13,37.75) U4.E3
  L5_SIG w0.165: v2(57.13,37.75) 57.53,38.15 60.61,38.15 61.41,38.95 62.51,38.95 65.32,41.76 65.32,51.27 62.32,54.27 v2(60.02,54.27)
DDR3_DQ12: length 29.5
  TOP w0.165: v2(56.33,37.75) U4.F3 ; v2(61.62,51.07) U2.A7
  L5_SIG w0.165: v2(61.62,51.07) 61.62,52.05 61.83,52.26 62.23,52.26 62.72,51.78 62.72,51.47 62.19,50.94 62.19,50.5 62.39,50.3 63.59,50.3 63.82,50.07 63.82,49.84 63.6,49.61 62.82,49.61 62.62,49.42 62.62,49.14 62.82,48.94 63.65,48.94 63.82,48.77 63.82,43.66 63.61,43.46 63.32,43.46 63.12,43.26 63.12,42.98 63.32,42.78 63.6,42.78 63.82,42.56 63.82,42.07 61.92,40.16 58.39,40.16 58.13,40.42 58.13,41.09 57.97,41.25 57.73,41.25 57.53,41.05 57.53,40.56 56.33,39.36 v2(56.33,37.75)
DDR3_DQ13: length 28.8
  TOP w0.165: v2(61.62,55.07) U2.A2 ; v2(55.13,42.45) 55.13,39.85 55.03,39.55 55.03,39.25 U4.G1
  L5_SIG w0.165: v2(55.13,42.45) 54.77,42.09 54.59,42.09 54.22,42.47 54.22,45.56 53.93,45.85 53.93,46.68 54.11,46.86 55.32,46.86 55.61,47.16 55.61,47.47 55.33,47.75 54.34,47.75 54.13,47.96 54.13,50.18 54.42,50.47 54.82,50.47 55.03,50.69 55.03,54.32 54.62,54.74 54.62,55.07 55.02,55.47 61.22,55.47 v2(61.62,55.07)
DDR3_DQ14: length 28.5
  TOP w0.165: v2(54.73,40.65) 54.33,40.25 U4.H1 ; v2(60.02,47.87) 60.82,48.67 60.82,49.47 U2.B8
  L5_SIG w0.165: v2(60.02,47.87) 59.72,47.58 59.54,47.58 59.42,47.7 59.42,50.17 59.26,50.33 58.98,50.33 58.82,50.17 58.82,46.37 58.62,46.17 58.42,46.17 58.22,46.37 58.22,47.17 58.02,47.37 57.72,47.37 57.53,47.17 57.53,46.37 57.33,46.17 56.77,46.17 56.54,45.93 56.54,45.7 56.77,45.47 58.47,45.47 58.72,45.22 58.72,44.94 58.52,44.75 56.26,44.75 56.03,44.52 56.03,44.2 56.26,43.97 57.11,43.97 57.32,43.77 57.32,43.54 57.15,43.37 56.82,43.37 56.62,43.17 56.62,42.84 54.73,40.95 v2(54.73,40.65)
DDR3_DQ15: length 31.7
  TOP w0.165: U4.H2 53.93,38.55 53.93,40.75 54.73,41.55 54.73,42.75 v2(55.13,43.15) ; v2(61.62,53.47) U2.A3
  L5_SIG w0.165: v2(55.13,43.15) 54.63,43.65 54.63,46.08 54.82,46.27 55.42,46.27 56.42,47.27 56.42,47.67 55.82,48.27 54.84,48.27 54.63,48.48 54.63,49.58 55,49.96 55.53,49.96 56.41,49.07 57.12,49.07 57.32,49.27 57.32,51.27 57.12,51.47 56.42,51.47 55.43,52.46 55.43,54.46 55.64,54.67 58.91,54.67 59.71,53.87 U2.A3 v2(61.62,53.47)
DDR3_DQS0_N: length 24.1
  TOP w0.127: U2.G3 56.82,53.47 v2(56.82,53.47) ; U4.B2 v2(59.53,38.55)
  L6_SIG w0.14: v2(56.82,53.47) 56.47,53.47 56.22,53.22 56.22,46.66 57.3,45.58 57.3,45.05 56.58,44.33 56.58,44.15 56.95,43.78 57.19,43.78 57.92,44.52 58.36,44.52 59.05,43.84 59.05,42.89 58.67,42.51 57.02,42.51 56.83,42.33 56.83,42.06 57.02,41.87 58.67,41.87 59.05,41.49 59.05,39.03 v2(59.53,38.55)
DDR3_DQS0_P: length 24.6
  TOP w0.127: U4.C2 v2(58.73,38.55) ; U2.F3 v2(56.82,54.27)
  L6_SIG w0.14: v2(58.73,38.55) 58.73,41.36 58.54,41.55 56.89,41.55 56.52,41.93 56.52,42.46 56.89,42.83 58.54,42.83 58.73,43.02 58.73,43.7 58.23,44.2 58.05,44.2 57.32,43.47 56.82,43.47 56.26,44.02 56.26,44.46 56.98,45.18 56.98,45.45 55.9,46.53 55.9,53.35 v2(56.82,54.27)
DDR3_DQS1_N: length 28.1
  TOP w0.127: U4.F2 v2(55.53,38.55) ; v2(60.82,51.07) U2.B7
  L5_SIG w0.14: v2(60.82,51.07) 60.34,50.59 60.34,50.3 60.94,49.7 60.94,48.4 61.16,48.17 61.86,48.17 62.32,47.71 62.32,47.07 61.91,46.66 60.46,46.66 60.24,46.43 60.24,46.11 60.46,45.89 61.71,45.89 62.2,45.39 62.2,43.95 61.8,43.55 60.83,43.55 59.91,44.48 59.5,44.48 59.13,44.1 59.13,43.83 60.3,42.65 60.3,42.07 59.89,41.65 59.3,41.65 58.13,42.83 57.76,42.83 55.63,40.71 55.63,40.23 55.05,39.64 55.05,38.87 55.16,38.76 55.32,38.76 v2(55.53,38.55)
DDR3_DQS1_P: length 27.7
  TOP w0.127: U4.G2 v2(54.73,38.55) ; U2.C7 v2(60.02,51.07)
  L5_SIG w0.14: v2(60.02,51.07) 60.02,50.17 60.62,49.57 60.62,48.27 61.03,47.85 61.72,47.85 62.01,47.57 62.01,47.2 61.78,46.98 60.33,46.98 59.92,46.56 59.92,45.98 60.33,45.57 61.58,45.57 61.89,45.26 61.89,44.08 61.67,43.87 60.96,43.87 60.04,44.79 59.37,44.79 58.81,44.23 58.81,43.7 59.98,42.52 59.98,42.2 59.76,41.97 59.44,41.97 58.26,43.15 57.63,43.15 55.31,40.84 55.31,40.36 54.73,39.77 v2(54.73,38.55)
DDR3_ODT: length 36.8
  TOP w0.165: U4.K3 v2(52.33,37.75) ; U2.K1 v2(53.62,55.87)
  L5_SIG w0.165: v2(53.62,55.87) 53.61,55.87 53.61,57.07 53.9,57.36 58.04,57.36 58.34,57.06 58.34,56.76 58.09,56.51 54.98,56.51 54.02,55.55 54.02,53.16 54.33,52.85 54.33,51.94 53.97,51.58 52.4,51.58 52.2,51.38 52.2,50.79 52.73,50.26 52.73,49.46 52.34,49.07 51.55,49.07 51.32,48.84 51.32,48.47 51.63,48.16 51.63,47.86 51.23,47.46 51.23,44.15 52.13,43.25 52.13,41.86 51.93,41.66 51.73,41.66 51.53,41.46 51.53,40.15 51.73,39.95 52.13,39.95 52.33,39.75 v2(52.33,37.75)
  BOTTOM w0.165: R33.1 54.32,55.6 54.19,55.47 54.01,55.47 v2(53.62,55.87)
DDR3_RAS#: length 28.5
  TOP w0.165: v2(48.22,34.95) 48.73,34.95 U4.R6 ; U2.J3 v2(54.42,53.47)
  L6_SIG w0.165: v2(54.42,53.47) 54.02,53.87 53.32,53.87 52.42,52.97 52.42,51.94 51.62,51.15 51.62,47.87 51.02,47.27 50.22,47.27 48.53,45.58 48.53,43.25 48.82,42.96 49.62,42.96 50.33,42.25 50.33,40.38 47.72,37.76 47.72,35.45 v2(48.22,34.95)
  BOTTOM w0.165: v2(54.42,53.47) 54.03,53.86 53.13,53.86 R37.1
DDR3_RST#: length 29
  TOP w0.165: U2.T2 48.02,55.87 v2(47.62,55.87) ; U4.L4 v2(51.53,36.95)
  L5_SIG w0.165: v2(44.32,52.02) 44.32,52.57 47.62,55.87 v2(47.62,55.87)
  BOTTOM w0.165: v2(51.53,36.95) 51.13,36.55 48.85,36.55 44.61,40.79 44.61,42.46 44.32,42.76 v2(44.32,52.02) ; R42.1 47.62,56.18 v2(47.62,55.87)
DDR3_WE#: length 28.9
  TOP w0.165: v2(45.61,38.26) 45.91,37.96 46.31,37.96 46.93,37.35 U4.R3 ; U2.L3 v2(53.62,54.27)
  L6_SIG w0.165: v2(53.62,54.27) 53.33,54.56 53.03,54.56 51.93,53.46 51.6,53.46 49.91,51.77 49.91,51.07 48.41,49.57 48.41,47.87 47.51,46.97 47.01,46.97 46.71,47.27 46.31,47.27 46.01,46.97 44.91,46.97 44.71,46.77 44.71,45.37 44.91,45.17 45.4,45.17 45.61,44.96 v2(45.61,38.26)
  BOTTOM w0.165: v2(53.62,54.27) 53.22,54.67 52.66,54.67 52.54,54.54 R31.1
FB0: length 5.9
  TOP w0.305: U3.4 v1(88.11,22.55)
  BOTTOM w0.305: v1(88.11,22.55) R2.2 86.35,23.33 85.7,22.68 85.7,21.13 R4.1
FB_1P8V: length 13.7
  TOP w0.203: v1(94.71,41.48) 94.37,41.82 U6.32
  BOTTOM w0.203: v1(94.71,41.48) 94.07,41.48 R65.2 88,41.36 84.68,38.05 R64.1
FB_1P35V: length 11.7
  TOP w0.305: v1(94.84,46.94) 94.62,46.72 U6.9
  BOTTOM w0.203: R63.1 94.84,46.24 v1(94.84,46.94) 94.84,47.95 94.08,48.71 88.36,48.71 87.98,49.1 R62.2
IO_02_34_AD9361_CLKOUT: length 27.2
  TOP w0.102: U5.J6 v2(27.55,32.88) ; U4.P8 49.13,33.75 47.83,33.75 v2(47.43,33.35)
  L6_SIG w0.114: v2(47.43,33.35) 46.92,33.85 45.73,33.85 43.1,36.48 30.47,36.48 29.55,35.55 29.55,34.28 29.35,34.08 28.95,34.08 28.75,33.88 28.75,33.48 28.55,33.28 27.95,33.28 v2(27.55,32.88)
  BOTTOM w0.102: AD9361_CLKOUT.1 v2(27.55,32.88)
IO_02_34_AD9361_RST: length 31.6
  TOP w0.102: U4.P9 49.13,32.95 47.82,32.95 v2(47.43,32.55) ; U5.K5 v2(26.74,33.68)
  L5_SIG w0.114: v2(47.43,32.55) 47.83,32.95 47.83,33.63 47.34,34.11 46.33,34.11 40.87,39.57 31.21,39.57 29.57,37.93 28.68,37.93 27.14,36.39 27.14,34.08 v2(26.74,33.68)
IO_L01_34_FB_CLK: length 27.3
  TOP w0.102: U5.F10 v2(30.74,28.88) ; v2(47.53,30.95) 47.93,31.34 49.13,31.34 U4.P10
  L6_SIG w0.114: v2(47.53,30.95) 48.26,30.22 48.26,28.78 47.96,28.48 47.96,27.23 47.4,26.67 47.15,26.67 46.07,25.6 32.36,25.6 31.15,26.81 31.15,28.48 v2(30.74,28.88)
IO_L01_34_RX_D0: length 50
  TOP w0.102: v2(54.73,28.15) U4.H14 ; v2(26.74,28.08) U5.K11
  L5_SIG w0.114: v2(26.74,28.08) 26.34,27.68 26.34,26.82 26.2,26.68 26.03,26.68 25.88,26.54 25.88,26.33 26.03,26.19 26.57,26.19 26.77,25.98 26.77,25.71 26.62,25.57 26.15,25.57 26.01,25.42 26.01,25.22 26.15,25.07 26.62,25.07 26.77,24.93 26.77,24.46 29.69,21.54 29.96,21.54 30.11,21.68 30.11,22.03 30.25,22.17 30.46,22.17 30.6,22.03 30.6,21.68 30.75,21.54 30.95,21.54 31.1,21.68 31.1,22.03 31.24,22.17 31.45,22.17 31.59,22.03 31.59,21.68 31.74,21.54 31.94,21.54 32.09,21.68 32.09,22.03 32.23,22.17 32.44,22.17 32.59,22.03 32.59,21.68 32.73,21.54 32.94,21.54 33.08,21.68 33.08,22.03 33.23,22.17 33.43,22.17 33.58,22.03 33.58,21.68 33.72,21.54 33.93,21.54 34.07,21.68 34.07,22.03 34.22,22.17 34.42,22.17 34.57,22.03 34.57,21.68 34.71,21.54 34.92,21.54 35.06,21.68 35.06,22.03 35.21,22.17 35.41,22.17 35.56,22.03 35.56,21.68 35.7,21.54 36.16,21.54 36.3,21.39 36.3,20.67 36.45,20.52 36.65,20.52 36.8,20.67 36.8,21.39 36.94,21.54 37.18,21.54 37.56,21.16 39.2,21.16 39.96,20.39 51.53,20.39 54.83,23.69 54.83,27.65 54.73,27.75 v2(54.73,28.15)
IO_L01_34_RX_D1: length 49.9
  TOP w0.102: U5.J12 27.55,27.28 v2(27.54,27.28) ; v2(53.93,28.94) U4.J13
  L5_SIG w0.114: v2(27.54,27.28) 27.54,25 28.97,23.57 30.06,23.57 30.2,23.71 30.2,24.06 30.35,24.2 30.55,24.2 30.7,24.06 30.7,23.71 30.84,23.57 31.05,23.57 31.2,23.71 31.2,24.06 31.34,24.2 31.55,24.2 31.69,24.06 31.69,23.71 31.84,23.57 32.04,23.57 32.19,23.71 32.19,24.06 32.33,24.2 32.54,24.2 32.68,24.06 32.68,23.71 32.83,23.57 33.03,23.57 33.18,23.71 33.18,24.06 33.32,24.2 33.53,24.2 33.67,24.06 33.67,23.71 33.82,23.57 34.02,23.57 34.17,23.71 34.17,24.06 34.31,24.2 34.52,24.2 34.66,24.06 34.66,23.71 34.81,23.57 35.01,23.57 35.16,23.71 35.16,24.06 35.3,24.2 35.51,24.2 35.65,24.06 35.65,23.71 35.8,23.57 36,23.57 36.15,23.71 36.15,24.06 36.29,24.2 36.5,24.2 36.64,24.06 36.64,23.71 36.79,23.57 37.03,23.57 37.17,23.71 37.17,24.06 37.32,24.2 37.52,24.2 37.67,24.06 37.67,23.34 37.82,23.19 38.06,23.19 38.73,23.85 38.93,23.85 39.08,23.71 39.08,23.5 38.62,23.05 38.62,22.84 38.76,22.7 38.97,22.7 39.43,23.15 39.63,23.15 39.78,23.01 39.78,22.8 39.32,22.35 39.32,22.14 39.46,22 39.67,22 40.13,22.45 40.33,22.45 40.48,22.31 40.48,22.1 40.02,21.65 40.02,21.44 40.3,21.16 51.03,21.16 53.53,23.66 53.53,27.75 53.93,28.15 v2(53.93,28.94)
IO_L02_34_RX_D2: length 50.2
  TOP w0.102: v2(55.53,28.15) U4.G14 ; U5.K10 v2(26.74,28.88)
  L5_SIG w0.114: v2(55.53,28.15) 55.93,27.75 55.93,23.52 52.04,19.63 33.88,19.63 33.5,20.01 33.5,20.65 33.37,20.77 33.01,20.77 32.87,20.63 32.87,20.03 32.72,19.89 32.52,19.89 32.37,20.03 32.37,20.63 32.23,20.77 32.02,20.77 31.88,20.63 31.88,20.03 31.73,19.89 31.53,19.89 31.38,20.03 31.38,20.63 31.24,20.77 29.18,20.77 24.86,25.09 24.86,25.73 25.12,25.98 25.12,26.36 24.86,26.62 24.86,27.02 25.12,27.27 25.12,27.51 24.86,27.77 24.86,28.01 25.54,28.69 25.54,29.07 25.74,29.27 26.35,29.27 v2(26.74,28.88)
IO_L02_34_RX_D3: length 49.9
  TOP w0.102: v2(27.54,28.07) U5.J11 ; U4.H13 v2(54.73,28.95)
  L5_SIG w0.114: v2(54.73,28.95) 54.23,28.45 54.23,27.95 53.93,27.65 53.93,23.42 51.28,20.77 40.22,20.77 39.07,21.92 38.91,21.92 38.59,21.6 38.39,21.6 38.24,21.75 38.24,21.95 38.58,22.29 38.58,22.43 38.45,22.55 37.57,22.55 37.43,22.41 37.43,22.06 37.28,21.92 37.08,21.92 36.93,22.06 36.93,23.04 36.79,23.19 36.58,23.19 36.44,23.04 36.44,22.06 36.29,21.92 36.09,21.92 35.94,22.06 35.94,22.41 35.8,22.55 35.29,22.55 35.14,22.7 35.14,23.04 35,23.19 34.79,23.19 34.65,23.04 34.65,22.7 34.5,22.55 34.3,22.55 34.15,22.7 34.15,23.04 34.01,23.19 33.8,23.19 33.66,23.04 33.66,22.7 33.51,22.55 33.31,22.55 33.16,22.7 33.16,23.04 33.02,23.19 32.81,23.19 32.67,23.04 32.67,22.7 32.52,22.55 32.32,22.55 32.17,22.7 32.17,23.04 32.03,23.19 31.82,23.19 31.68,23.04 31.68,22.7 31.53,22.55 31.33,22.55 31.18,22.7 31.18,23.04 31.04,23.19 30.83,23.19 30.69,23.04 30.69,22.7 30.54,22.55 30.34,22.55 30.19,22.7 30.19,23.04 30.05,23.19 29.84,23.19 29.7,23.04 29.7,22.7 29.55,22.55 29.31,22.55 27.14,24.72 27.14,27.68 v2(27.54,28.07)
IO_L03_34_RX_D4: length 51.6
  TOP w0.102: U5.K9 v2(26.74,29.68) ; U4.G12 v2(55.53,29.75)
  L5_SIG w0.114: v2(26.74,29.68) 26.35,30.07 24.93,30.07 24.48,29.63 24.48,24.84 30.07,19.25 52.3,19.25 56.73,23.68 56.73,27.35 55.93,28.15 55.93,29.14 55.73,29.35 55.6,29.35 55.53,29.42 v2(55.53,29.75)
IO_L03_34_RX_D5: length 50.6
  TOP w0.102: U4.H12 v2(54.73,29.75) ; U5.J10 v2(27.55,28.88)
  L5_SIG w0.114: v2(54.73,29.75) 55.13,29.35 55.13,23.35 51.79,20.01 39.74,20.01 38.98,20.77 37.56,20.77 36.93,20.14 36.04,20.14 35.91,20.27 35.91,21.03 35.79,21.16 35.52,21.16 35.37,21.01 35.37,20.28 35.23,20.14 35.02,20.14 34.88,20.28 34.88,21.01 34.73,21.16 34.53,21.16 34.38,21.01 34.38,20.28 34.24,20.14 34.03,20.14 33.89,20.28 33.89,21.01 33.74,21.16 29.44,21.16 25.53,25.07 25.53,28.26 25.74,28.47 27.14,28.47 27.54,28.88 v2(27.55,28.88)
IO_L04_34_RX_D6: length 55.4
  TOP w0.102: U5.K8 v2(26.74,30.48) ; U4.G11 v2(55.53,30.55)
  L5_SIG w0.114: v2(55.53,30.55) 55.93,30.15 55.93,29.55 56.13,29.35 56.53,29.35 56.73,29.15 56.73,27.95 57.03,27.65 57.27,27.65 57.53,27.39 57.53,23.85 52.55,18.87 29.82,18.87 24.1,24.58 24.1,29.79 25.19,30.87 26.35,30.87 v2(26.74,30.48)
IO_L04_34_RX_D7: length 49.6
  TOP w0.102: v2(53.13,28.15) U4.J14 ; U5.J9 v2(27.54,30.48)
  L5_SIG w0.114: v2(27.54,30.48) 27.54,29.97 28.21,29.31 28.21,25.44 28.55,25.09 28.85,25.09 28.99,25.24 28.99,26.22 29.14,26.36 29.34,26.36 29.49,26.22 29.49,25.24 29.63,25.09 31.06,25.09 31.6,25.63 31.6,26.22 31.75,26.36 31.95,26.36 32.1,26.22 32.1,25.75 32.24,25.6 32.45,25.6 32.59,25.75 32.59,26.22 32.74,26.36 32.94,26.36 33.09,26.22 33.09,25.75 33.23,25.6 33.44,25.6 33.58,25.75 33.58,26.22 33.73,26.36 33.93,26.36 34.08,26.22 34.08,25.75 34.22,25.6 34.43,25.6 34.57,25.75 34.57,26.22 34.72,26.36 34.92,26.36 35.07,26.22 35.07,25.75 35.21,25.6 35.42,25.6 35.56,25.75 35.56,26.22 35.71,26.36 35.91,26.36 36.06,26.22 36.06,25.75 36.2,25.6 37.99,25.6 38.13,25.46 38.13,25.11 38.28,24.97 38.48,24.97 38.63,25.11 38.63,25.46 38.77,25.6 39.72,25.6 41.81,23.51 41.81,23.31 41.38,22.88 41.38,22.67 41.53,22.53 41.73,22.53 42.16,22.96 42.37,22.96 42.51,22.81 42.51,22.61 42.21,22.3 42.21,22.1 42.36,21.95 42.56,21.95 42.86,22.26 43.07,22.26 43.41,21.92 50.52,21.92 52.73,24.13 52.73,27.75 v2(53.13,28.15)
IO_L05_34_RX_D8: length 49.1
  TOP w0.102: v2(53.13,27.35) U4.J15 ; U5.K7 v2(26.74,31.28)
  L5_SIG w0.114: v2(26.74,31.28) 27.14,30.88 27.14,29.94 27.96,29.12 27.96,25.17 28.42,24.71 30.07,24.71 30.2,24.58 32.15,24.58 32.32,24.75 32.32,25.04 32.42,25.14 32.72,25.14 32.82,25.04 32.82,24.71 32.94,24.58 33.15,24.58 33.29,24.73 33.29,25.07 33.44,25.22 33.64,25.22 33.79,25.07 33.79,24.73 33.93,24.58 34.14,24.58 34.28,24.73 34.28,25.07 34.43,25.22 34.63,25.22 34.78,25.07 34.78,24.73 34.92,24.58 35.13,24.58 35.27,24.73 35.27,25.07 35.42,25.22 35.62,25.22 35.77,25.07 35.77,24.73 35.91,24.58 36.12,24.58 36.26,24.73 36.26,25.07 36.41,25.22 36.61,25.22 36.76,25.07 36.76,24.73 36.9,24.58 37.11,24.58 37.25,24.73 37.25,25.07 37.4,25.22 37.6,25.22 37.75,25.07 37.75,24.73 37.89,24.58 39.04,24.58 39.41,24.95 39.61,24.95 39.76,24.81 39.76,24.6 39.39,24.23 39.39,24.03 39.54,23.88 39.74,23.88 40.11,24.25 40.31,24.25 40.46,24.11 40.46,23.9 40.09,23.53 40.09,23.33 40.24,23.18 40.44,23.18 40.81,23.55 41.01,23.55 41.16,23.4 41.16,23.2 40.79,22.83 40.79,22.63 41.07,22.35 41.07,22.15 40.83,21.91 40.83,21.7 40.97,21.56 41.18,21.56 41.42,21.8 41.62,21.8 41.88,21.54 50.77,21.54 53.13,23.89 v2(53.13,27.35)
IO_L05_34_RX_D9: length 49
  TOP w0.102: v2(52.33,27.35) U4.K15 ; U5.J8 v2(27.54,31.28)
  L5_SIG w0.114: v2(27.54,31.28) 27.95,30.88 27.95,30.08 28.41,29.61 28.41,29.6 28.45,29.57 28.45,26.97 28.67,26.74 29.82,26.74 30.07,27 30.33,27 30.59,26.73 30.59,25.62 30.74,25.47 30.94,25.47 31.09,25.62 31.09,26.6 31.23,26.74 35.11,26.74 35.25,26.89 35.25,28.7 35.4,28.85 35.6,28.85 35.75,28.7 35.75,26.89 35.89,26.74 36.3,26.74 36.45,26.6 36.45,26.13 36.59,25.98 36.8,25.98 36.94,26.13 36.94,26.5 37.09,26.64 37.29,26.64 37.44,26.5 37.44,26.13 37.58,25.98 37.79,25.98 37.93,26.13 37.93,27.5 38.08,27.64 38.28,27.64 38.43,27.5 38.43,26.13 38.57,25.98 38.78,25.98 38.92,26.13 38.92,27.5 39.07,27.64 39.31,27.64 39.47,27.49 39.47,26.16 39.64,25.98 39.98,25.98 43.66,22.3 50.26,22.3 52.33,24.36 v2(52.33,27.35)
IO_L06_34_RX_D10: length 49.2
  TOP w0.102: U4.H11 v2(54.73,30.55) ; U5.J7 v2(28.35,31.28)
  L5_SIG w0.114: v2(28.35,31.28) 28.35,30.02 28.75,29.62 28.75,28.59 29.66,27.68 34.14,27.68 34.35,27.88 34.35,28.48 35.15,29.28 35.99,29.28 36.13,29.13 36.13,27.27 36.28,27.12 36.48,27.12 36.63,27.27 36.63,29.13 36.77,29.28 36.98,29.28 37.12,29.13 37.12,28.16 37.27,28.01 37.47,28.01 37.62,28.16 37.62,29.13 37.76,29.28 37.97,29.28 38.11,29.13 38.11,28.16 38.26,28.01 38.46,28.01 38.61,28.16 38.61,29.13 38.76,29.28 38.97,29.28 39.09,29.16 39.09,28.39 39.85,27.63 39.85,26.66 43.84,22.68 49.88,22.68 51.53,24.33 51.53,28.05 52.03,28.55 53.33,28.55 53.53,28.75 53.53,29.16 53.81,29.44 53.81,29.63 v2(54.73,30.55)
IO_L06_34_RX_D11: length 52.4
  TOP w0.102: U5.H8 v2(29.15,31.28) ; U4.J11 v2(53.13,30.55)
  L5_SIG w0.114: v2(29.15,31.28) 29.55,30.88 29.55,28.67 29.74,28.48 30.95,28.48 31.15,28.68 31.15,29.88 31.35,30.08 31.74,30.08 31.94,29.88 31.94,28.68 32.14,28.48 32.54,28.48 32.74,28.68 32.74,29.88 32.94,30.08 33.35,30.08 33.54,29.88 33.54,29.48 33.74,29.28 34.15,29.28 34.35,29.48 34.35,29.88 34.55,30.08 35.95,30.08 36.35,30.48 36.86,30.48 37,30.33 37,29.81 37.15,29.66 37.35,29.66 37.5,29.81 37.5,30.33 37.64,30.48 37.9,30.48 38.07,30.3 38.07,29.79 38.2,29.66 39.22,29.66 39.45,29.43 39.45,28.58 40.23,27.79 40.23,26.87 40.4,26.7 40.61,26.7 40.91,27 41.12,27 41.26,26.86 41.26,26.65 40.96,26.35 40.96,26.14 41.1,26 41.31,26 41.61,26.3 41.82,26.3 41.96,26.16 41.96,25.95 41.66,25.65 41.66,25.44 41.8,25.3 42.01,25.3 42.31,25.6 42.52,25.6 42.66,25.46 42.66,25.25 42.36,24.95 42.36,24.74 42.5,24.6 42.71,24.6 43.01,24.9 43.22,24.9 43.36,24.76 43.36,24.55 43.06,24.25 43.06,24.04 43.53,23.57 44.57,23.57 44.71,23.71 44.71,24.06 44.86,24.2 45.06,24.2 45.21,24.06 45.21,23.71 45.35,23.57 45.82,23.57 45.96,23.42 45.96,23.21 46.11,23.06 46.31,23.06 46.46,23.21 46.46,23.42 46.6,23.57 47.32,23.57 47.47,23.42 47.47,23.21 47.61,23.06 47.82,23.06 47.97,23.21 47.97,23.42 48.11,23.57 48.32,23.57 48.46,23.42 48.46,23.21 48.61,23.06 48.81,23.06 48.96,23.21 48.96,23.42 49.1,23.57 50.14,23.57 51.15,24.58 51.15,28.17 51.83,28.85 51.83,29.15 52.03,29.35 53.38,29.35 53.57,29.54 53.57,30.43 53.45,30.55 v2(53.13,30.55)
IO_L07_34_RX_FRAME: length 56
  TOP w0.102: v2(49.93,28.95) U4.N13 ; U5.G8 v2(29.95,31.28)
  L5_SIG w0.114: v2(49.93,28.95) 49.93,25.9 50.36,25.47 50.36,24.77 49.86,24.27 46.13,24.27 45.61,24.8 45.61,25 45.91,25.31 45.91,25.51 45.77,25.66 45.56,25.66 45.26,25.35 45.05,25.35 44.91,25.5 44.91,25.7 45.21,26.01 45.21,26.21 45.07,26.36 44.86,26.36 44.56,26.05 44.35,26.05 44.21,26.2 44.21,26.4 44.91,27.11 44.91,27.31 44.77,27.46 44.56,27.46 43.86,26.75 43.65,26.75 43.41,27 43.41,29.13 41.8,30.73 41.6,30.73 41.18,30.32 40.98,30.32 40.83,30.46 40.83,30.67 41.25,31.08 41.25,31.29 41.1,31.43 40.9,31.43 40.48,31.02 40.28,31.02 39.78,31.51 39.78,31.79 39.92,31.93 40.84,31.93 40.99,32.08 40.99,32.28 40.84,32.43 39.92,32.43 39.78,32.57 39.78,32.78 39.92,32.93 40.34,32.93 40.49,33.07 40.49,33.28 40.34,33.42 39.43,33.42 39.28,33.28 39.28,32.35 39.14,32.2 38.93,32.2 38.79,32.35 38.79,33.68 38.64,33.82 38.44,33.82 38.29,33.68 38.29,32.35 38.15,32.2 37.94,32.2 37.8,32.35 37.8,33.68 37.65,33.82 37.45,33.82 37.3,33.68 37.3,32.35 37.16,32.2 36.95,32.2 36.81,32.35 36.81,33.23 36.66,33.37 35.64,33.37 35.45,33.18 35.45,32.94 35.59,32.79 36.2,32.79 36.35,32.65 36.35,32.44 36.2,32.3 35.59,32.3 35.45,32.15 35.45,31.88 35.25,31.68 35.06,31.68 34.79,31.95 34.55,31.95 34.28,31.68 34.07,31.68 33.93,31.82 33.93,32.23 33.78,32.38 33.58,32.38 33.43,32.23 33.43,31.82 33.29,31.68 33.08,31.68 32.94,31.82 32.94,32.23 32.79,32.38 32.59,32.38 32.44,32.23 32.44,31.82 32.3,31.68 32.09,31.68 31.95,31.82 31.95,32.23 31.8,32.38 31.6,32.38 31.45,32.23 31.45,31.82 31.31,31.68 30.35,31.68 v2(29.95,31.28)
IO_L08_34_CTRL_OUT0: length 30.4
  TOP w0.102: U4.L15 51.93,27.04 49.97,25.08 48.09,25.08 v2(47.13,26.05) ; U5.D4 v2(32.34,34.48)
  L5_SIG w0.114: v2(47.13,26.05) 47.13,27.94 46.83,28.25 46.23,28.25 45.95,28.52 45.95,29.02 42.52,32.45 42.52,34.11 40.99,35.63 35.91,35.63 35.07,36.48 32.95,36.48 32.75,36.28 32.75,34.88 v2(32.34,34.48)
IO_L08_34_CTRL_OUT1: length 31.1
  TOP w0.102: U4.M15 51.13,27.04 49.76,25.67 49.1,25.67 v2(48.73,26.05) ; U5.E4 v2(31.54,34.48)
  L5_SIG w0.114: v2(48.73,26.05) 48.73,28.55 48.23,29.05 46.83,29.05 45.73,30.15 45.33,30.15 43.62,31.85 43.62,32.75 42.9,33.47 42.9,34.24 41.12,36.01 36.42,36.01 35.15,37.28 32.15,37.28 31.95,37.08 31.95,34.88 v2(31.54,34.48)
IO_L09_34_TX_FRAME: length 28.7
  TOP w0.102: v2(52.33,28.15) U4.L14 ; v2(29.94,30.48) U5.G9
  L6_SIG w0.114: v2(52.33,28.15) 49.4,25.22 32.34,25.22 31.38,26.18 31.14,26.18 30.34,26.98 30.34,30.08 v2(29.94,30.48)
IO_L10_34_EN_AGC: length 35.1
  TOP w0.102: U4.L13 51.46,28.88 51.46,26.97 49.86,25.37 48.6,25.37 v2(47.93,26.05) ; U5.G5 v2(29.14,33.68)
  L5_SIG w0.114: v2(47.93,26.05) 47.45,25.57 46.9,25.57 46.63,25.84 46.63,26.84 45.13,28.35 45.13,29.35 42.14,32.33 42.14,33.98 40.87,35.25 34.01,35.25 33.65,34.89 33.65,34.28 33.45,34.08 32.15,34.08 30.55,32.48 29.75,32.48 29.55,32.68 29.55,33.28 v2(29.14,33.68)
IO_L11_34_ENABLE: length 30.7
  TOP w0.102: U4.K12 v2(52.33,29.75) ; U5.G6 v2(29.14,32.88)
  L6_SIG w0.114: v2(52.33,29.75) 51.93,30.15 51.33,30.15 51.13,30.35 51.13,32.35 50.13,33.35 49.33,33.35 48.83,33.85 48.12,33.85 47.83,33.55 47.83,33.15 47.63,32.95 47.23,32.95 46.63,33.55 45.53,33.55 43.4,35.68 31.35,35.68 31.15,35.48 31.15,35.08 30.15,34.08 29.75,34.08 29.55,33.88 29.55,33.28 v2(29.14,32.88)
IO_L11_34_TXNRX: length 32.7
  TOP w0.102: U5.H4 v2(28.35,34.48) ; U4.K11 v2(52.33,30.55)
  L6_SIG w0.114: v2(52.33,30.55) 51.93,30.95 51.93,33.95 51.73,34.15 45.93,34.15 42.16,37.92 29.48,37.92 28.75,37.18 28.75,34.88 v2(28.35,34.48)
IO_L12_MRCC_34_DATA_CLK: length 55.5
  TOP w0.102: U5.G11 v2(29.95,28.88) ; U4.L12 v2(51.53,29.75)
  L5_SIG w0.114: v2(51.53,29.75) 51.53,29.05 50.77,28.29 50.77,24.69 50.03,23.95 45.95,23.95 44.55,25.35 44.34,25.35 43.91,24.92 43.71,24.92 43.56,25.06 43.56,25.27 43.99,25.7 43.99,25.9 43.85,26.05 43.64,26.05 43.21,25.62 43.01,25.62 42.86,25.76 42.86,25.97 43.29,26.4 43.29,26.6 43.15,26.75 42.94,26.75 42.51,26.32 42.31,26.32 42.16,26.47 42.16,26.67 42.97,27.48 42.97,27.69 42.83,27.83 42.62,27.83 41.81,27.02 41.61,27.02 41.46,27.17 41.46,27.37 42.4,28.31 42.4,28.51 42.25,28.66 42.05,28.66 40.98,27.59 40.78,27.59 40.63,27.74 40.63,27.94 42.08,29.39 42.08,29.6 41.89,29.78 41.68,29.78 40.32,28.42 40.11,28.42 39.97,28.56 39.97,28.77 40.74,29.54 40.74,29.92 40.5,30.16 40.29,30.16 39.93,29.79 39.72,29.79 39.58,29.94 39.58,30.14 39.94,30.51 39.94,30.72 39.8,30.86 39.59,30.86 38.97,30.24 38.77,30.24 38.62,30.39 38.62,30.59 39.24,31.21 39.24,31.54 38.96,31.82 38.45,31.82 38.31,31.68 38.31,31.02 38.16,30.88 37.92,30.88 37.78,31.02 37.78,31.68 37.63,31.82 37.43,31.82 37.28,31.68 37.28,31.02 37.14,30.88 36.93,30.88 36.79,31.02 36.79,31.68 36.64,31.82 36.43,31.82 36.29,31.68 36.29,30.9 36.14,30.75 35.94,30.75 35.79,30.9 35.79,31.17 35.65,31.32 35.44,31.32 35.3,31.17 35.3,31.02 35.15,30.88 30.55,30.88 30.35,30.68 30.35,29.28 v2(29.95,28.88)
IO_L13_34_CTRL_OUT2: length 29.4
  TOP w0.102: U5.E5 v2(30.74,33.68) ; U4.N11 v2(49.93,30.55)
  L5_SIG w0.114: v2(30.74,33.68) 30.74,34.68 30.25,35.18 30.25,36.28 30.44,36.48 30.94,36.48 31.21,36.75 31.21,37.28 31.98,38.05 35.41,38.05 36.71,36.75 41.41,36.75 43.53,34.62 43.53,33.94 44.22,33.25 44.52,33.25 44.93,32.85 44.93,32.25 46.13,31.05 46.13,30.75 47.13,29.74 47.83,29.74 48.63,30.55 v2(49.93,30.55)
IO_L13_34_CTRL_OUT3: length 30.3
  TOP w0.102: U5.E6 v2(31.54,32.88) ; U4.N12 v2(49.93,29.75)
  L5_SIG w0.114: v2(31.54,32.88) 31.94,33.28 33.55,33.28 34.05,33.78 34.05,34.53 34.39,34.87 39.6,34.87 41.37,33.1 41.37,32.1 41.82,31.65 42.32,31.65 44.83,29.15 44.83,28.1 46.23,26.7 46.23,25.74 46.78,25.19 48.58,25.19 49.13,25.74 49.13,28.95 v2(49.93,29.75)
IO_L15_34_TX_D0: length 23.4
  TOP w0.102: U4.P15 49.53,27.45 49.15,27.07 45.51,27.07 v2(45.31,26.87) ; U5.E12 31.22,27.6 31.22,27.58 v2(31.53,27.27)
  L6_SIG w0.114: v2(45.31,26.87) 45.95,26.87 46.2,26.62 46.2,26.36 45.82,25.98 43.49,25.98 43.23,26.24 42.78,26.24 42.52,25.98 42.15,25.98 41.89,26.24 41.44,26.24 41.19,25.98 40.82,25.98 40.56,26.24 40.11,26.24 39.85,25.98 39.48,25.98 39.22,26.24 38.77,26.24 38.52,25.98 38.14,25.98 37.88,26.24 37.43,26.24 37.18,25.98 36.8,25.98 36.55,26.24 36.1,26.24 35.84,25.98 32.44,25.98 31.53,26.89 v2(31.53,27.27)
